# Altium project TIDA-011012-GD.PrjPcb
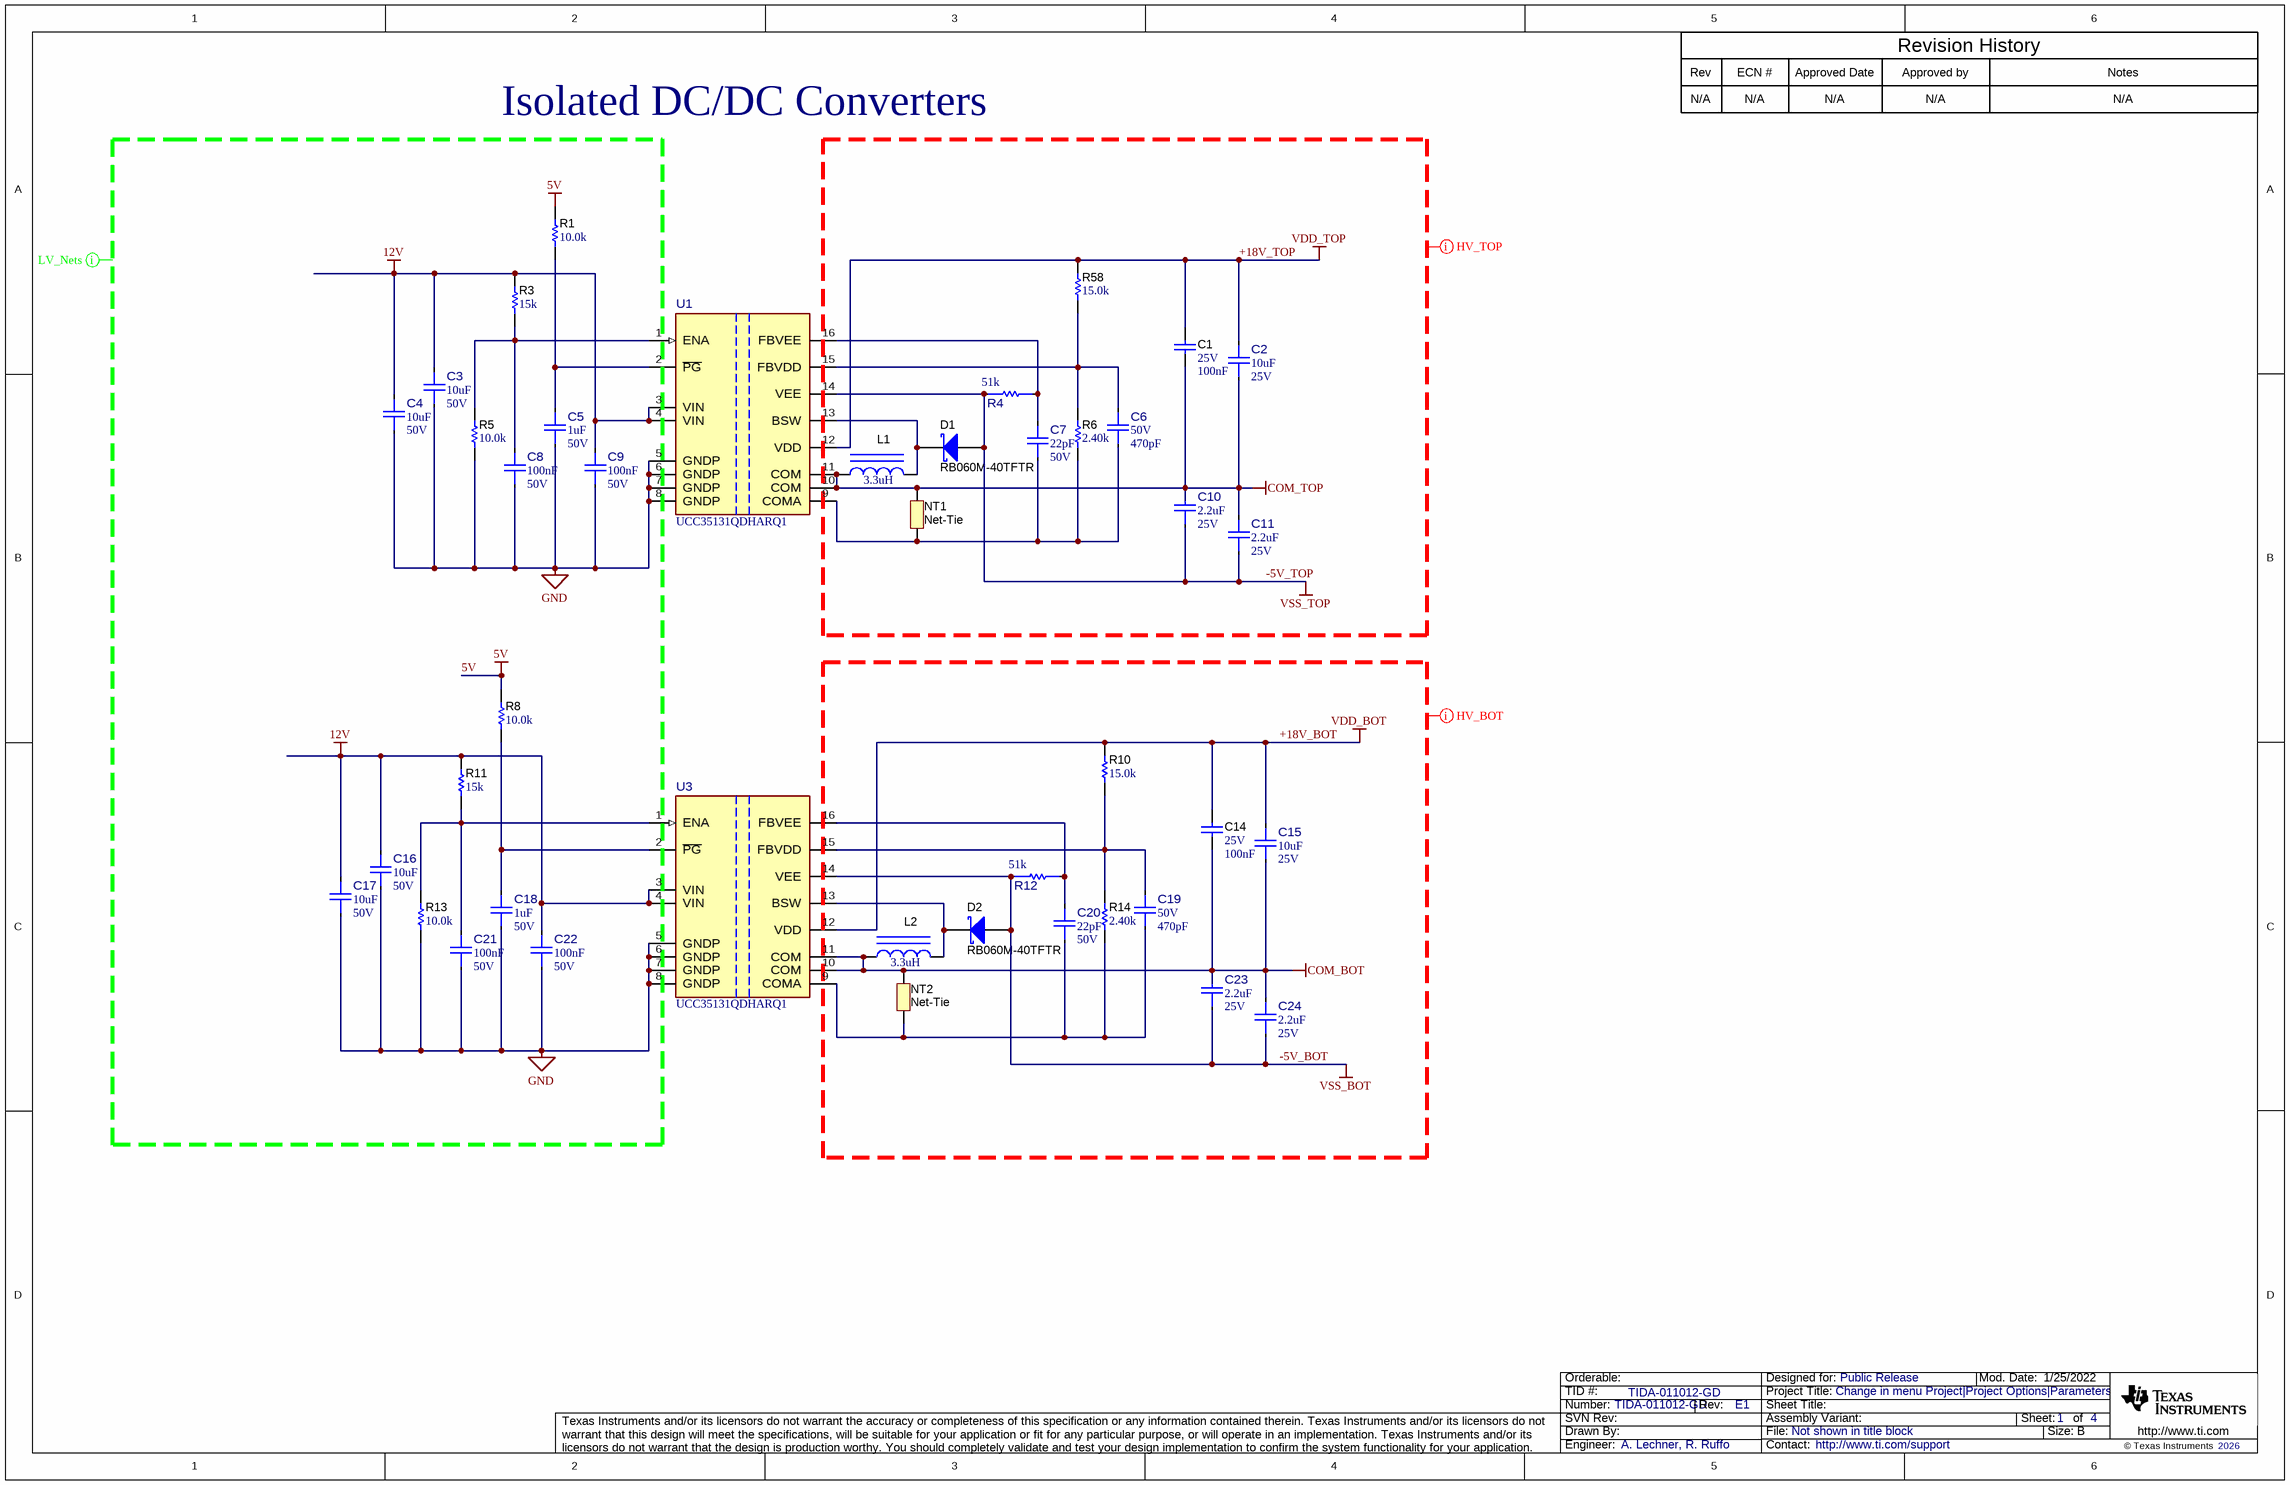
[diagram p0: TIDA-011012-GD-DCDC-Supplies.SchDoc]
TID: TIDA-011012-GD; TechSupport: http://www.ti.com/support; SCH_Rev: E1; PRJ_Title: Change in menu Project|Project Options|Parameters; PRJ_Number: TIDA-011012-GD; PRJ_Engineer: A. Lechner, R. Ruffo; PRJ_Customer: Public Release; PCB_Rev: E1; CopyrightYear: 2026
3 sheets, 153 parts. Net scope: global (net labels, ports and power ports of the same name join across sheets).
Board file: TIDA-011012-GD.PcbDoc
Sheets:
  TIDA-011012-GD-DCDC-Supplies.SchDoc
  TIDA-011012-GD-Gate-Drivers.SchDoc
  TIDA-011012-GD-Hardware.SchDoc

## Sheet TIDA-011012-GD-DCDC-Supplies.SchDoc
size 431 x 279 mm; Date: Not shown in title block; ApprovedBy: Not shown in title block; CheckedBy: Not shown in title block; Author: Not shown in title block; CompanyName: Not shown in title block; Engineer: Not shown in title block; Organization: Not shown in title block; Address1: Not shown in title block; Address2: Not shown in title block; Address3: Not shown in title block; Address4: Not shown in title block; DocumentNumber: 1; Revision: Use project parameter SCH_Rev; SheetNumber: 1; SheetTotal: 4; PageSetup: Record=PageOptions¦CenterHorizontal=True¦CenterVertical=True¦PrintScale=1.00¦XCorrection=1.00¦YCorrection=1.00¦PrintKind=0¦BorderSize=5000000¦LeftOffset=0¦BottomOffset=0¦Orientation=2¦PaperLength=1000¦PaperWidth=1000¦Scale=100¦PaperSource=15¦PrintQuality=600¦MediaType=1¦DitherType=10¦PaperKind=Letter¦PrintScaleMode=1

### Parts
C1  VDC_V: 25V  Cap_F: 100nF  [0603]  (hidden comment: GCM188R71E104KA57D)
C2  ValueDisplayed: 10uF  VDC_V: 25V  [FP-KGM31HR71E106KU_1206-MFG]  (hidden comment: KGM31HR71E106KU)
C3  ValueDisplayed: 10uF  VDC_V: 50V  [FP-GMC31X7R106K50NT_1206-MFG]  (hidden comment: GMC31X7R106K50NT)
C4  ValueDisplayed: 10uF  VDC_V: 50V  [FP-GMC31X7R106K50NT_1206-MFG]  (hidden comment: GMC31X7R106K50NT)
C5  ValueDisplayed: 1uF  VDC_V: 50V  [FP-C1206C105J5RECAUTO_1206-MFG]  (hidden comment: C1206C105J5RECAUTO)
C6  VDC_V: 50V  ValueDisplayed: 470pF  [FP-C0603X471F5GACTU_0603-MFG]  (hidden comment: C0603X471F5GACTU)
C7  ValueDisplayed: 22pF  VDC_V: 50V  [FP-VJ0603D220JLAAJ32_0603-IPC_C]  (hidden comment: VJ0603D220JLAAJ32)
C8  Cap_F: 100nF  VDC_V: 50V  [FP-KGM15BR71H104JT_0603-MFG]  (hidden comment: KGM15BR71H104JT)
C9  Cap_F: 100nF  VDC_V: 50V  [FP-KGM15BR71H104JT_0603-MFG]  (hidden comment: KGM15BR71H104JT)
C10  ValueDisplayed: 2.2uF  VDC_V: 25V  [FP-GRT188C71E225KE13D_0603-MFG]  (hidden comment: GRT188C71E225KE13D)
C11  ValueDisplayed: 2.2uF  VDC_V: 25V  [FP-CGA5L2X7R1E225K160AA_1206-MFG]  (hidden comment: CGA5L2X7R1E225K160AA)
C14  VDC_V: 25V  Cap_F: 100nF  [0603]  (hidden comment: GCM188R71E104KA57D)
C15  ValueDisplayed: 10uF  VDC_V: 25V  [FP-KGM31HR71E106KU_1206-MFG]  (hidden comment: KGM31HR71E106KU)
C16  ValueDisplayed: 10uF  VDC_V: 50V  [FP-GMC31X7R106K50NT_1206-MFG]  (hidden comment: GMC31X7R106K50NT)
C17  ValueDisplayed: 10uF  VDC_V: 50V  [FP-GMC31X7R106K50NT_1206-MFG]  (hidden comment: GMC31X7R106K50NT)
C18  ValueDisplayed: 1uF  VDC_V: 50V  [FP-C1206C105J5RECAUTO_1206-MFG]  (hidden comment: C1206C105J5RECAUTO)
C19  VDC_V: 50V  ValueDisplayed: 470pF  [FP-C0603X471F5GACTU_0603-MFG]  (hidden comment: C0603X471F5GACTU)
C20  ValueDisplayed: 22pF  VDC_V: 50V  [FP-VJ0603D220JLAAJ32_0603-IPC_C]  (hidden comment: VJ0603D220JLAAJ32)
C21  Cap_F: 100nF  VDC_V: 50V  [FP-KGM15BR71H104JT_0603-MFG]  (hidden comment: KGM15BR71H104JT)
C22  Cap_F: 100nF  VDC_V: 50V  [FP-KGM15BR71H104JT_0603-MFG]  (hidden comment: KGM15BR71H104JT)
C23  ValueDisplayed: 2.2uF  VDC_V: 25V  [FP-GRT188C71E225KE13D_0603-MFG]  (hidden comment: GRT188C71E225KE13D)
C24  ValueDisplayed: 2.2uF  VDC_V: 25V  [FP-CGA5L2X7R1E225K160AA_1206-MFG]  (hidden comment: CGA5L2X7R1E225K160AA)
D1  RB060M-40TFTR  [SOD-123]
D2  RB060M-40TFTR  [SOD-123]
L1  ValueDisplayed: 3.3uH  [0603]  (hidden comment: AIML-0603-3R3K-T)
L2  ValueDisplayed: 3.3uH  [0603]  (hidden comment: AIML-0603-3R3K-T)
NT1  Net-Tie  [Net-Tie_0805_HV_NoOverlay]  (net tie, no BOM)
NT2  Net-Tie  [Net-Tie_0805_HV_NoOverlay]  (net tie, no BOM)
R1  ValueDisplayed: 10.0k  [0603]  (hidden comment: ERJ-3EKF1002V)
R3  ValueDisplayed: 15k  [0603]  (hidden comment: RC0603JR-0715KL)
R4  value 51k  [FP-ERA-3AED513V_0603-MFG]  (hidden comment: ERA-3AED513V)
R5  ValueDisplayed: 10.0k  [0603]  (hidden comment: RT0603DRE0710KL)
R6  ValueDisplayed: 2.40k  [0603]  (hidden comment: RT0603DRE072K4L)
R8  ValueDisplayed: 10.0k  [0603]  (hidden comment: ERJ-3EKF1002V)
R10  ValueDisplayed: 15.0k  [0603]  (hidden comment: RT0603BRD0715KL)
R11  ValueDisplayed: 15k  [0603]  (hidden comment: RC0603JR-0715KL)
R12  value 51k  [FP-ERA-3AED513V_0603-MFG]  (hidden comment: ERA-3AED513V)
R13  ValueDisplayed: 10.0k  [0603]  (hidden comment: RT0603DRE0710KL)
R14  ValueDisplayed: 2.40k  [0603]  (hidden comment: RT0603DRE072K4L)
R58  ValueDisplayed: 15.0k  [0603]  (hidden comment: RT0603BRD0715KL)
U1  UCC35131QDHARQ1  [DHA0016A-MFG]
U3  UCC35131QDHARQ1  [DHA0016A-MFG]

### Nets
5V: R1.2 R8.2
12V: C3.2 C4.2 C9.2 C16.2 C17.2 C22.2 R3.2 R11.2 U1.3(VIN) U1.4(VIN) U3.3(VIN) U3.4(VIN)
+18V_BOT: C14.1 C15.2 R10.2 U3.12(VDD)  [also labelled VDD_BOT]
+18V_TOP: C1.1 C2.2 R58.2 U1.12(VDD)  [also labelled VDD_TOP]
-5V_BOT: C23.1 C24.1 D2.2(A) R12.1 U3.14(VEE)  [also labelled VSS_BOT]
-5V_TOP: C10.1 C11.1 D1.2(A) R4.1 U1.14(VEE)  [also labelled VSS_TOP]
COM_BOT: C14.2 C15.1 C23.2 C24.2 L2.1 NT2.2 U3.10(COM) U3.11(COM)  [project net KS2]
COM_TOP: C1.2 C2.1 C10.2 C11.2 L1.1 NT1.2 U1.10(COM) U1.11(COM)  [project net KS1]
GND: C3.1 C4.1 C5.1 C8.1 C9.1 C16.1 C17.1 C18.1 C21.1 C22.1 R5.1 R13.1 U1.5(GNDP) U1.6(GNDP) U1.7(GNDP) U1.8(GNDP) U3.5(GNDP) U3.6(GNDP) U3.7(GNDP) U3.8(GNDP)
NetC5_2: C5.2 R1.1 U1.2(~{PG})
NetC6_1: C6.1 C7.1 NT1.1 R6.1 U1.9(COMA)
NetC6_2: C6.2 R6.2 R58.1 U1.15(FBVDD)
NetC7_2: C7.2 R4.2 U1.16(FBVEE)
NetC8_2: C8.2 R3.1 R5.2 U1.1(ENA)
NetC18_2: C18.2 R8.1 U3.2(~{PG})
NetC19_1: C19.1 C20.1 NT2.1 R14.1 U3.9(COMA)
NetC19_2: C19.2 R10.1 R14.2 U3.15(FBVDD)
NetC20_2: C20.2 R12.2 U3.16(FBVEE)
NetC21_2: C21.2 R11.1 R13.2 U3.1(ENA)
NetD1_1: D1.1(K) L1.2 U1.13(BSW)
NetD2_1: D2.1(K) L2.2 U3.13(BSW)

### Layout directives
net class LV: 5V, 12V, GND
net class HV_TOP: +18V_TOP, -5V_TOP, COM_TOP, VDD_TOP, VSS_TOP
net class HV_BOT: +18V_BOT, -5V_BOT, COM_BOT, VDD_BOT, VSS_BOT

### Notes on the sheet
- Rev
- N/A
- ECN #
- Approved Date
- Approved by
- Revision History
- Notes
- Isolated DC/DC Converters

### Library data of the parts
C1 C14 = CMP-0084679-1: CAP, CERM, 0.1 µF, 25 V,+/- 10%, X7R, AEC-Q200 Grade 1, 0603; Manufacturer: MuRata; TaMin_C: -55°C; SizeY_mm: 0.8; Polarized: N; SizeArea_mm2: 1.28; SizeZ_mm: 1; SizeX_mm: 1.6; AEC Qualified: Y; AEC Category: Q200; Value: 0.1uF; ValueDisplayed: 0.1µF; TaMax_C: 125°C; U/M: EA; SizeAreaWB_mm2: 4.68
C2 C15 = CMP-0044202-1: 10 µF ±10% 25V Ceramic Capacitor X7R 1206 (3216 Metric); Manufacturer: KYOCERA AVX; AEC Qualified: No; Cap_F: 10µF; SizeZ_mm: 1.9mm; TempCo: 15%; Value: 10µF
C3 C4 C16 C17 = CMP-0093201-1: 10 µF ±10% 50V Ceramic Capacitor X7R 1206 (3216 Metric); Manufacturer: Cal-Chip Electronics; AEC Qualified: No; SizeZ_mm: 1.8mm; TempCo: 15%; Value: 10µF
C5 C18 = CMP-0094524-1: 1 µF ±5% 50V Ceramic Capacitor X7R 1206 (3216 Metric); Manufacturer: KEMET; TempCo: 15%; Cap_F: 1µF; AEC Grade: Grade 1; AEC Qualified: Yes; SizeZ_mm: 1.1mm; Value: 1µF
C6 C19 = CMP-0097612-1: Cap Ceramic 470pF 50V C0G 1% SMD 0603 125°C Paper T/R; Manufacturer: KEMET; SizeZ_mm: 0.95mm; TempCo: 30ppm/°C; AEC Qualified: No
C7 C20 = CMP-0039814-1: 22 pF ±5% 50V Ceramic Capacitor C0G, NP0 0603 (1608 Metric); Manufacturer: Vishay; AEC Grade: Grade 0; AEC Qualified: Yes; SizeZ_mm: 0.97mm; TempCo: 30ppm/°C; Value: 22pF
C8 C9 C21 C22 = CMP-0120061-1: 0.1 µF ±5% 50V Ceramic Capacitor X7R 0603 (1608 Metric); Manufacturer: KYOCERA AVX; AEC Qualified: No; SizeZ_mm: 0.94mm; TempCo: 15%; ValueDisplayed: 0.1uF; Value: 100nF
C10 C23 = CMP-0125378-1: Multi-Layer Ceramic Capacitor 2.2uF 25V X7S ±10% 0603 Paper T/R; Manufacturer: Murata; AEC Grade: Grade 1; AEC Qualified: Yes; Cap_F: 2.2µF; SizeZ_mm: 1mm; TempCo: 22%; Value: 2.2µF
C11 C24 = CMP-0090741-1: Cap Ceramic 2.2uF 25V X7R 10% Pad SMD 1206 +125°C Automotive T/R; Manufacturer: TDK; Cap_F: 2.2µF; Value: 2.2µF; Tolerance_%: 0.1%; TempCo: 15%; AEC Grade: Grade 1; AEC Qualified: Yes; SizeZ_mm: 1.9mm
D1 D2 = CMP-0028628-2: Diode, Schottky, 40 V, 2 A, SOD-123; Manufacturer: Rohm; Green_REACh: Incomplete; SizeX_mm: 3.85; SizeZ_mm: 1.35; TJmax_C: 150°C; Value1: 2A; SizeAreaWB_mm2: 13.095; SizeArea_mm2: 6.545; AEC Category: Q101; Value2: 0.56V; SizeY_mm: 1.7; Value: 40V; Vf_V: 560mV; Green_Lifecycle: Not Set
L1 L2 = CMP-0059575-1: Inductor, Multilayer, Ferrite, 3.3 uH, 0.015 A, 1.55 ohm, SMD; Manufacturer: Abracon Corporation; Green_Lifecycle: Active; SizeAreaWB_mm2: 4.68; DCR_ohm: 1.55; Green_REACh: Passed; Value: 3.3uH; Imax_A: 15mA; SizeZ_mm: 1; SizeX_mm: 1.6; SizeY_mm: 0.8; Value2: 0.015A; SizeArea_mm2: 1.28; Ind_H: 3.3µH; AEC Qualified: N; AEC Category: Q200
NT1 NT2 = CMP-0078142-6: Single point connection between nets.
R1 R8 = CMP-0022684-3: RES, 10.0 k, 1%, 0.1 W, 0603; Manufacturer: Panasonic; Power_W: 100mW; TempCo: 100 ppm/C; Value_Code: 10k0; U/M: EA; Value: 10.0k; EIA_Code: E96; Res_ohm: 10k; SizeX_mm: 1.6; SizeY_mm: 0.8; SizeZ_mm: 1; Value2: 0.1W; SizeArea_mm2: 1.28; VDC_V: 75V; AEC Category: Q200
R3 R11 = CMP-0025890-5: RES, 15 k, 5%, 0.1 W, 0603; Manufacturer: Yageo; Power_W: 100mW; TempCo: 100 ppm/C; Value_Code: 15k0; Value: 15k; EIA_Code: E24; SizeX_mm: 1.6; SizeY_mm: 0.8; SizeZ_mm: 1; Value2: 0.1W; SizeArea_mm2: 1.28; AEC Qualified: N; VDC_V: 75V; AEC Category: Q200; SizeAreaWB_mm2: 4.68
R4 R12 = CMP-0031881-1: 51 kOhms ±0.5% 0.1W, 1/10W Chip Resistor 0603 (1608 Metric) Automotive AEC-Q200 Thin Film; Manufacturer: Panasonic; AEC Grade: Grade 0; AEC Qualified: Yes; Power_W: 100mW; SizeZ_mm: 0.55mm; TempCo: 25ppm/°C; VDC_V: 75V
R5 R13 = CMP-0024586-3: RES, 10.0 k, 0.5%, 0.1 W, 0603; Manufacturer: Yageo America; Power_W: 100mW; TempCo: 50 ppm/C; Value_Code: 10k0; U/M: EA; Value: 10.0k; EIA_Code: E192; Res_ohm: 10k; SizeX_mm: 1.6; SizeY_mm: 0.8; SizeZ_mm: 1; Value2: 0.1W; SizeArea_mm2: 1.28; VDC_V: 75V; AEC Category: Q200
R6 R14 = CMP-0025064-3: RES, 2.40 k, 0.5%, 0.1 W, 0603; Manufacturer: Yageo America; Power_W: 100mW; TempCo: 50 ppm/C; Value_Code: 2k40; U/M: EA; Value: 2.40k; EIA_Code: E192; Res_ohm: 2.4k; SizeX_mm: 1.6; SizeY_mm: 0.8; SizeZ_mm: 1; Value2: 0.1W; SizeArea_mm2: 1.28; VDC_V: 75V; AEC Category: Q200
R10 R58 = CMP-0023780-3: RES, 15.0 k, 0.1%, 0.1 W, 0603; Manufacturer: Yageo America; Power_W: 100mW; TempCo: 25 ppm/C; Value_Code: 15k0; U/M: EA; Value: 15.0k; EIA_Code: E192; Res_ohm: 15k; SizeX_mm: 1.6; SizeY_mm: 0.8; SizeZ_mm: 1; Value2: 0.1W; SizeArea_mm2: 1.28; VDC_V: 75V; AEC Category: Q200
U1 U3 = CMP-0126653-2: Automotive 2.0W, 12V VIN, High-Density, > 5kVRMS, Isolated DC/DC Module; Manufacturer: Texas Instruments; SizeZ_mm: 2.6mm; AEC Qualified: Yes; AEC Grade: Grade 1; Max Supply Voltage: 20V; Min Supply Voltage: 5.5V; Number Of Outputs: 2; Output Type: AdjustableProgrammable; Output Voltage: -2-8/12-18V; Standoff Height: 0.1mm; TaMax_C: +125°C; TaMin_C: -40°C; TJmax_C: +150°C; AEC Category: Q200; CompType: IC

## Sheet TIDA-011012-GD-Gate-Drivers.SchDoc
size 558 x 431 mm; Date: Not shown in title block; ApprovedBy: Not shown in title block; CheckedBy: Not shown in title block; Author: Not shown in title block; CompanyName: Not shown in title block; Engineer: Not shown in title block; Organization: Not shown in title block; Address1: Not shown in title block; Address2: Not shown in title block; Address3: Not shown in title block; Address4: Not shown in title block; DocumentNumber: 2; Revision: Use project parameter SCH_Rev; SheetNumber: 2; SheetTotal: 3; PageSetup: Record=PageOptions¦CenterHorizontal=True¦CenterVertical=True¦PrintScale=1.00¦XCorrection=1.00¦YCorrection=1.00¦PrintKind=0¦BorderSize=5000000¦LeftOffset=0¦BottomOffset=0¦Orientation=2¦PaperLength=1000¦PaperWidth=1000¦Scale=100¦PaperSource=15¦PrintQuality=600¦MediaType=1¦DitherType=10¦PaperKind=Letter¦PrintScaleMode=1
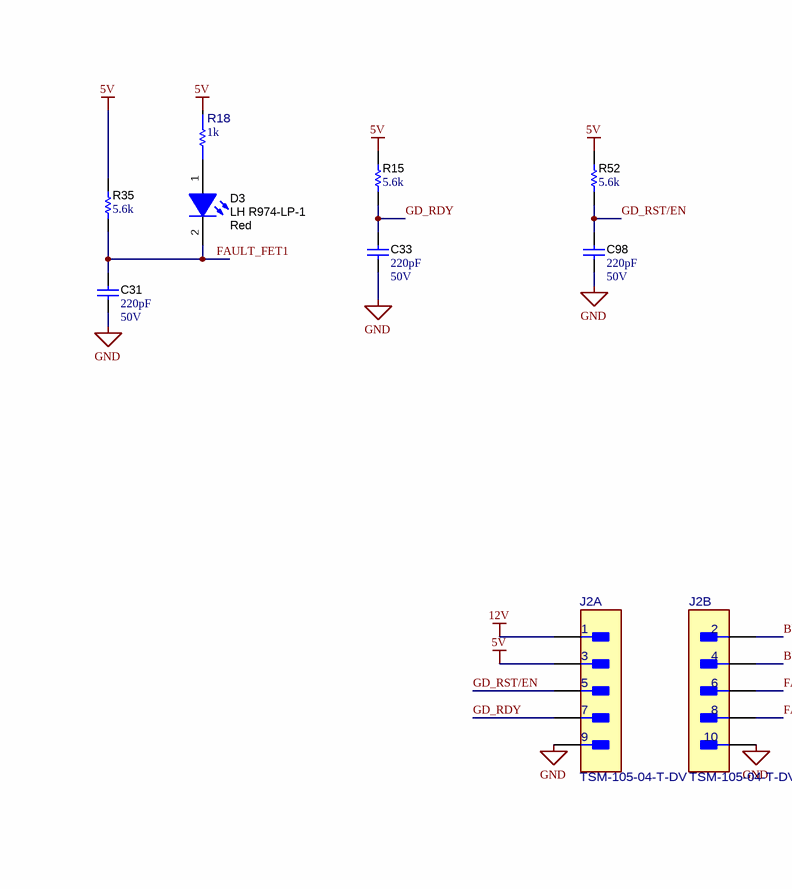
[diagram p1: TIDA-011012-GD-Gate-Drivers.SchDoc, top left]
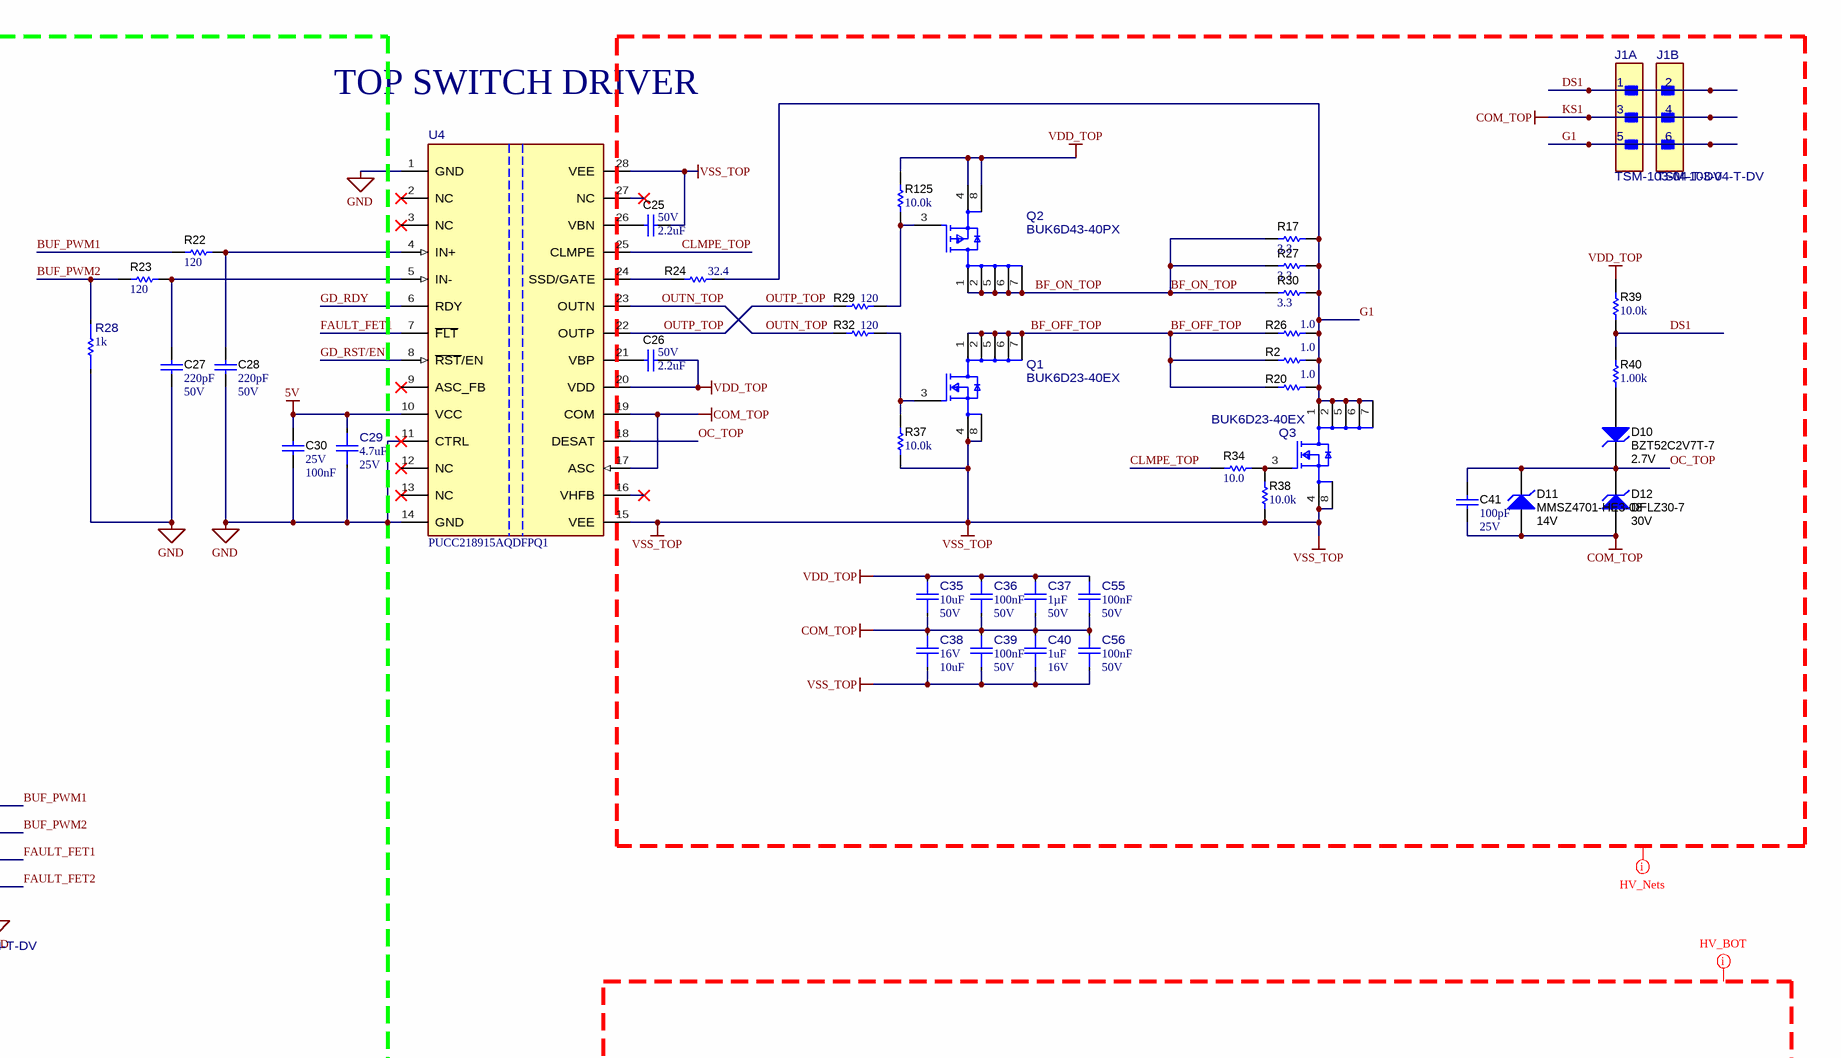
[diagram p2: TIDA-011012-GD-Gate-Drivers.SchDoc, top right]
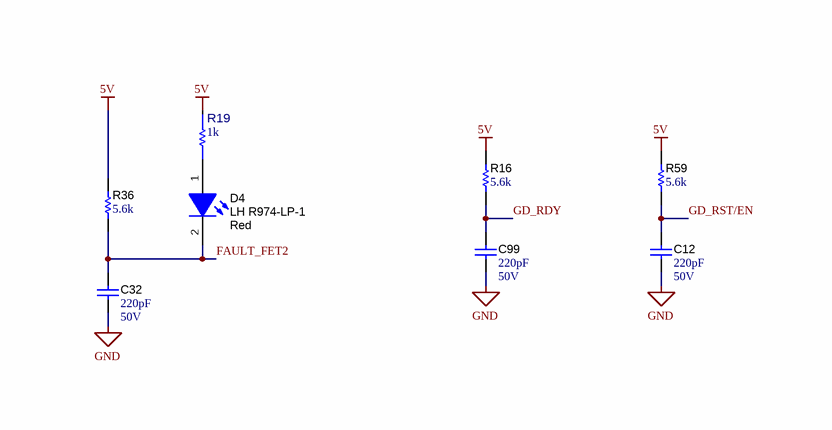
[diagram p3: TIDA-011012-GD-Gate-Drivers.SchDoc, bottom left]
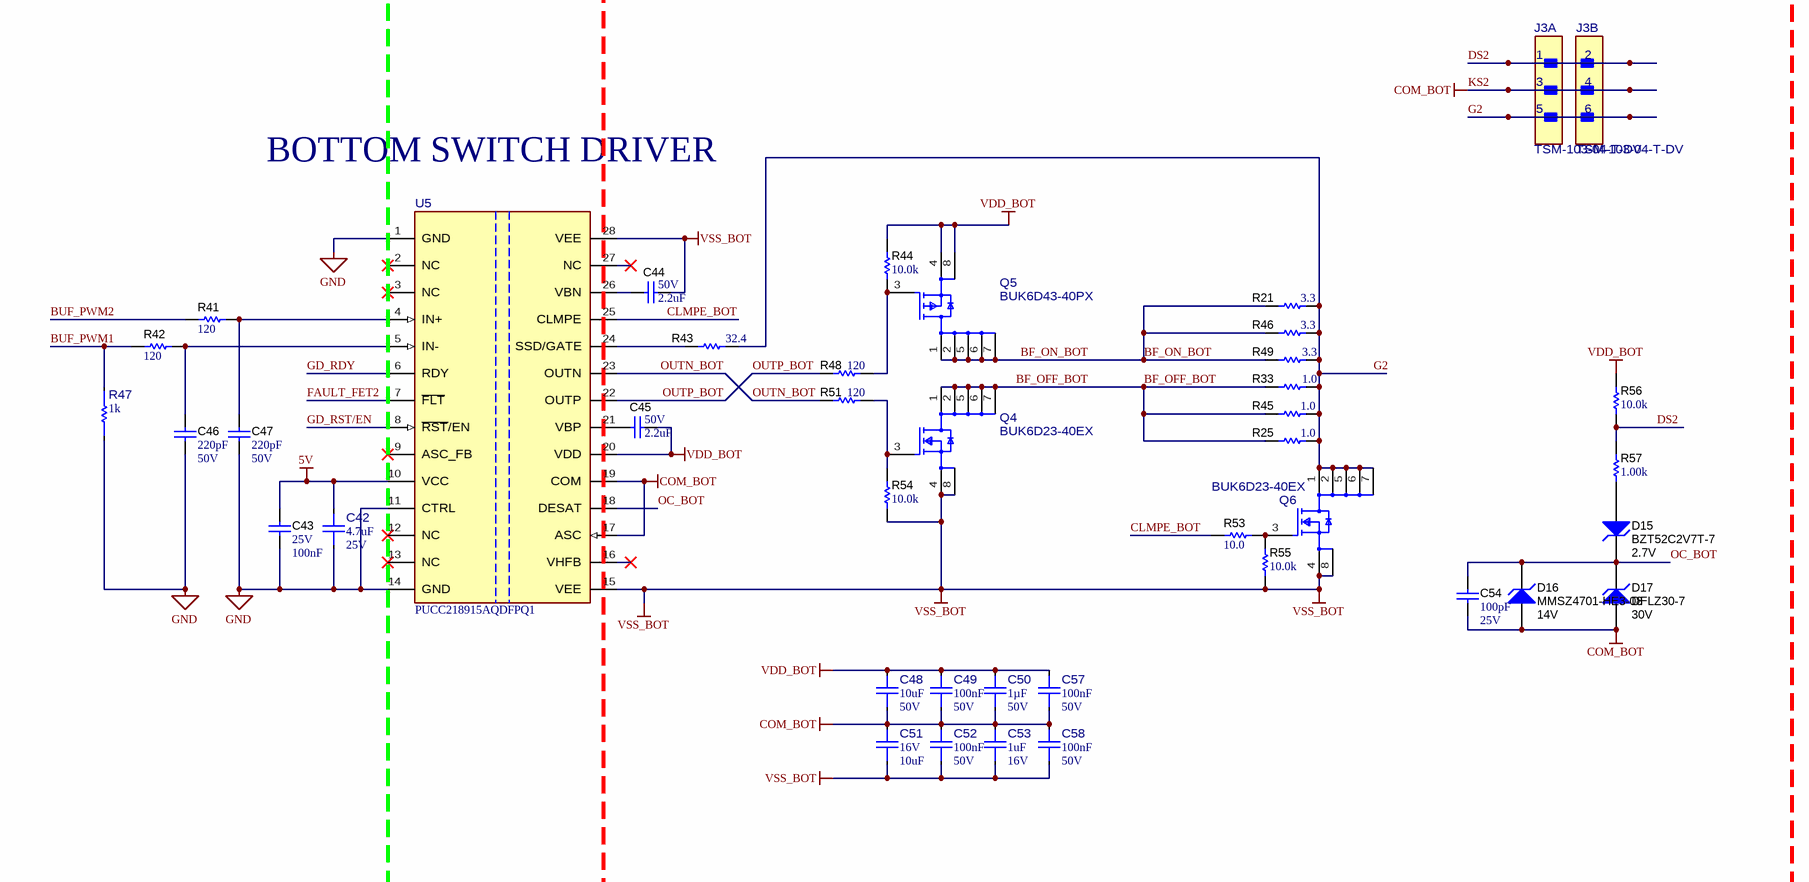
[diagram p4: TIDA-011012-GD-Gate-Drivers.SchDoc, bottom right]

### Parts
C12  Cap_F: 220pF  VDC_V: 50V  [0603]  (hidden comment: C0603C221K5RACTU)
C25  VDC_V: 50V  ValueDisplayed: 2.2uF  [0603]  (hidden comment: GRT188R61H225KE13D)
C26  VDC_V: 50V  ValueDisplayed: 2.2uF  [0603]  (hidden comment: GRT188R61H225KE13D)
C27  Cap_F: 220pF  VDC_V: 50V  [0603]  (hidden comment: C0603C221K5RACTU)
C28  Cap_F: 220pF  VDC_V: 50V  [0603]  (hidden comment: C0603C221K5RACTU)
C29  ValueDisplayed: 4.7uF  VDC_V: 25V  [FP-GRM188R61E475KE15D_0603-MFG]  (hidden comment: GRM188R61E475KE15D)
C30  VDC_V: 25V  Cap_F: 100nF  [0603]  (hidden comment: GCM188R71E104KA57D)
C31  Cap_F: 220pF  VDC_V: 50V  [0603]  (hidden comment: C0603C221K5RACTU)
C32  Cap_F: 220pF  VDC_V: 50V  [0603]  (hidden comment: C0603C221K5RACTU)
C33  Cap_F: 220pF  VDC_V: 50V  [0603]  (hidden comment: C0603C221K5RACTU)
C35  ValueDisplayed: 10uF  VDC_V: 50V  [FP-GMC31X7R106K50NT_1206-MFG]  (hidden comment: GMC31X7R106K50NT)
C36  Cap_F: 100nF  VDC_V: 50V  [FP-C0805C104K5RAC7800_0805-MFG]  (hidden comment: C0805C104K5RAC7800)
C37  Cap_F: 1µF  VDC_V: 50V  [FP-CL10B105KB9VPJC_0603-MFG]  (hidden comment: CL10B105KB9VPJC)
C38  VDC_V: 16V  ValueDisplayed: 10uF  [FP-C1206C106J4RACAUTO_1206-MFG]  (hidden comment: C1206C106J4RACAUTO)
C39  Cap_F: 100nF  VDC_V: 50V  [FP-C0805C104K5RAC7800_0805-MFG]  (hidden comment: C0805C104K5RAC7800)
C40  ValueDisplayed: 1uF  VDC_V: 16V  [FP-GRM188C71C105KA12D_0603-MFG]  (hidden comment: GRM188C71C105KA12D)
C41  Cap_F: 100pF  VDC_V: 25V  [0603]  (hidden comment: 06033C101KAT2A)
C42  ValueDisplayed: 4.7uF  VDC_V: 25V  [FP-GRM188R61E475KE15D_0603-MFG]  (hidden comment: GRM188R61E475KE15D)
C43  VDC_V: 25V  Cap_F: 100nF  [0603]  (hidden comment: GCM188R71E104KA57D)
C44  VDC_V: 50V  ValueDisplayed: 2.2uF  [0603]  (hidden comment: GRT188R61H225KE13D)
C45  VDC_V: 50V  ValueDisplayed: 2.2uF  [0603]  (hidden comment: GRT188R61H225KE13D)
C46  Cap_F: 220pF  VDC_V: 50V  [0603]  (hidden comment: C0603C221K5RACTU)
C47  Cap_F: 220pF  VDC_V: 50V  [0603]  (hidden comment: C0603C221K5RACTU)
C48  ValueDisplayed: 10uF  VDC_V: 50V  [FP-GMC31X7R106K50NT_1206-MFG]  (hidden comment: GMC31X7R106K50NT)
C49  Cap_F: 100nF  VDC_V: 50V  [FP-C0805C104K5RAC7800_0805-MFG]  (hidden comment: C0805C104K5RAC7800)
C50  Cap_F: 1µF  VDC_V: 50V  [FP-CL10B105KB9VPJC_0603-MFG]  (hidden comment: CL10B105KB9VPJC)
C51  VDC_V: 16V  ValueDisplayed: 10uF  [FP-C1206C106J4RACAUTO_1206-MFG]  (hidden comment: C1206C106J4RACAUTO)
C52  Cap_F: 100nF  VDC_V: 50V  [FP-C0805C104K5RAC7800_0805-MFG]  (hidden comment: C0805C104K5RAC7800)
C53  ValueDisplayed: 1uF  VDC_V: 16V  [FP-GRM188C71C105KA12D_0603-MFG]  (hidden comment: GRM188C71C105KA12D)
C54  Cap_F: 100pF  VDC_V: 25V  [0603]  (hidden comment: 06033C101KAT2A)
C55  Cap_F: 100nF  VDC_V: 50V  [FP-C0603C104K5RAC3121_0603-MFG]  (hidden comment: C0603C104K5RAC3121)
C56  Cap_F: 100nF  VDC_V: 50V  [FP-C0603C104K5RAC3121_0603-MFG]  (hidden comment: C0603C104K5RAC3121)
C57  Cap_F: 100nF  VDC_V: 50V  [FP-C0603C104K5RAC3121_0603-MFG]  (hidden comment: C0603C104K5RAC3121)
C58  Cap_F: 100nF  VDC_V: 50V  [FP-C0603C104K5RAC3121_0603-MFG]  (hidden comment: C0603C104K5RAC3121)
C98  Cap_F: 220pF  VDC_V: 50V  [0603]  (hidden comment: C0603C221K5RACTU)
C99  Cap_F: 220pF  VDC_V: 50V  [0603]  (hidden comment: C0603C221K5RACTU)
D3  LH R974-LP-1  value Red  [LH_R974_Red]
D4  LH R974-LP-1  value Red  [LH_R974_Red]
D10  BZT52C2V7T-7  value 2.7V  [SOD-523]
D11  MMSZ4701-HE3-08  value 14V  [SOD-123]
D12  DFLZ30-7  value 30V  [PowerDI123]
D15  BZT52C2V7T-7  value 2.7V  [SOD-523]
D16  MMSZ4701-HE3-08  value 14V  [SOD-123]
D17  DFLZ30-7  value 30V  [PowerDI123]
J1  TSM-103-04-T-DV  [FP-TSM-103-04-T-DV_HDR10-MFG]  (parts A,B of 2)
J2  TSM-105-04-T-DV  [FP-TSM-105-04-T-DV_HDR10-MFG]  (parts A,B of 2)
J3  TSM-103-04-T-DV  [FP-TSM-103-04-T-DV_HDR10-MFG]  (parts A,B of 2)
Q1  BUK6D23-40EX  [FP-BUK6D23-40EX_SOT1220-MFG]
Q2  BUK6D43-40PX  [FP-BUK6D43-40PX_SOT1220-MFG]
Q3  BUK6D23-40EX  [FP-BUK6D23-40EX_SOT1220-MFG]
Q4  BUK6D23-40EX  [FP-BUK6D23-40EX_SOT1220-MFG]
Q5  BUK6D43-40PX  [FP-BUK6D43-40PX_SOT1220-MFG]
Q6  BUK6D23-40EX  [FP-BUK6D23-40EX_SOT1220-MFG]
R2  ValueDisplayed: 1.0  [1206]  (hidden comment: CRM1206-JW-1R0ELF)
R15  ValueDisplayed: 5.6k  [0603]  (hidden comment: RC0603JR-075K6L)
R16  ValueDisplayed: 5.6k  [0603]  (hidden comment: RC0603JR-075K6L)
R17  ValueDisplayed: 3.3  [1206]  (hidden comment: CRCW12063R30JNEA)
R18  Res_ohm: 1k  [FP-ERJ-3GEYJ102V_0603-MFG]  (hidden comment: ERJ-3GEYJ102V)
R19  Res_ohm: 1k  [FP-ERJ-3GEYJ102V_0603-MFG]  (hidden comment: ERJ-3GEYJ102V)
R20  ValueDisplayed: 1.0  [1206]  (hidden comment: CRM1206-JW-1R0ELF)
R21  ValueDisplayed: 3.3  [1206]  (hidden comment: CRCW12063R30JNEA)
R22  ValueDisplayed: 120  [0603]  (hidden comment: RT0603BRD07120RL)
R23  ValueDisplayed: 120  [0603]  (hidden comment: RT0603BRD07120RL)
R24  ValueDisplayed: 32.4  [1206]  (hidden comment: CRCW120632R4FKEA)
R25  ValueDisplayed: 1.0  [1206]  (hidden comment: CRM1206-JW-1R0ELF)
R26  ValueDisplayed: 1.0  [1206]  (hidden comment: CRM1206-JW-1R0ELF)
R27  ValueDisplayed: 3.3  [1206]  (hidden comment: CRCW12063R30JNEA)
R28  Res_ohm: 1k  [FP-ERJ-3GEYJ102V_0603-MFG]  (hidden comment: ERJ-3GEYJ102V)
R29  ValueDisplayed: 120  [0603]  (hidden comment: RT0603BRD07120RL)
R30  ValueDisplayed: 3.3  [1206]  (hidden comment: CRCW12063R30JNEA)
R32  ValueDisplayed: 120  [0603]  (hidden comment: RT0603BRD07120RL)
R33  ValueDisplayed: 1.0  [1206]  (hidden comment: CRM1206-JW-1R0ELF)
R34  ValueDisplayed: 10.0  [0603]  (hidden comment: RC0603FR-0710RL)
R35  ValueDisplayed: 5.6k  [0603]  (hidden comment: RC0603JR-075K6L)
R36  ValueDisplayed: 5.6k  [0603]  (hidden comment: RC0603JR-075K6L)
R37  ValueDisplayed: 10.0k  [0603]  (hidden comment: ERJ-3EKF1002V)
R38  ValueDisplayed: 10.0k  [0603]  (hidden comment: ERJ-3EKF1002V)
R39  ValueDisplayed: 10.0k  [0603]  (hidden comment: ERJ-3EKF1002V)
R40  ValueDisplayed: 1.00k  [0603]  (hidden comment: ERJ-3EKF1001V)
R41  ValueDisplayed: 120  [0603]  (hidden comment: RT0603BRD07120RL)
R42  ValueDisplayed: 120  [0603]  (hidden comment: RT0603BRD07120RL)
R43  ValueDisplayed: 32.4  [1206]  (hidden comment: CRCW120632R4FKEA)
R44  ValueDisplayed: 10.0k  [0603]  (hidden comment: ERJ-3EKF1002V)
R45  ValueDisplayed: 1.0  [1206]  (hidden comment: CRM1206-JW-1R0ELF)
R46  ValueDisplayed: 3.3  [1206]  (hidden comment: CRCW12063R30JNEA)
R47  Res_ohm: 1k  [FP-ERJ-3GEYJ102V_0603-MFG]  (hidden comment: ERJ-3GEYJ102V)
R48  ValueDisplayed: 120  [0603]  (hidden comment: RT0603BRD07120RL)
R49  ValueDisplayed: 3.3  [1206]  (hidden comment: CRCW12063R30JNEA)
R51  ValueDisplayed: 120  [0603]  (hidden comment: RT0603BRD07120RL)
R52  ValueDisplayed: 5.6k  [0603]  (hidden comment: RC0603JR-075K6L)
R53  ValueDisplayed: 10.0  [0603]  (hidden comment: RC0603FR-0710RL)
R54  ValueDisplayed: 10.0k  [0603]  (hidden comment: ERJ-3EKF1002V)
R55  ValueDisplayed: 10.0k  [0603]  (hidden comment: ERJ-3EKF1002V)
R56  ValueDisplayed: 10.0k  [0603]  (hidden comment: ERJ-3EKF1002V)
R57  ValueDisplayed: 1.00k  [0603]  (hidden comment: ERJ-3EKF1001V)
R59  ValueDisplayed: 5.6k  [0603]  (hidden comment: RC0603JR-075K6L)
R125  ValueDisplayed: 10.0k  [0603]  (hidden comment: ERJ-3EKF1002V)
U4  PUCC218915AQDFPQ1  [DFP0028A-MFG]
U5  PUCC218915AQDFPQ1  [DFP0028A-MFG]

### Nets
5V: C29.2 C30.2 C42.2 C43.2 J2.3 R15.2 R16.2 R18.1 R19.1 R35.2 R36.2 R52.2 R59.2 U4.10(VCC) U5.10(VCC)
12V: J2.1
GND: C12.2 C27.2 C28.2 C29.1 C30.1 C31.2 C32.2 C33.2 C42.1 C43.1 C46.2 C47.2 C98.2 C99.2 J2.9 J2.10 R28.2 R47.2 U4.1(GND) U4.11(CTRL) U4.14(GND) U5.1(GND) U5.11(CTRL) U5.14(GND)
KS1: C35.1 C36.1 C37.1 C38.2 C39.2 C40.2 C41.2 C55.1 C56.2 D11.2(A) D12.2(A) J1.3 J1.4 U4.17(ASC) U4.19(COM)  [also labelled COM_TOP]
KS2: C48.1 C49.1 C50.1 C51.2 C52.2 C53.2 C54.2 C57.1 C58.2 D16.2(A) D17.2(A) J3.3 J3.4 U5.17(ASC) U5.19(COM)  [also labelled COM_BOT]
VDD_BOT: C45.1 C48.2 C49.2 C50.2 C57.2 Q5.4(S) Q5.8(S) R44.2 R56.2 U5.20(VDD)  [project net +18V_BOT]
VDD_TOP: C26.1 C35.2 C36.2 C37.2 C55.2 Q2.4(S) Q2.8(S) R39.2 R125.2 U4.20(VDD)  [project net +18V_TOP]
VSS_BOT: C44.1 C51.1 C52.1 C53.1 C58.1 Q4.4(S) Q4.8(S) Q6.4(S) Q6.8(S) R54.1 R55.2 U5.15(VEE) U5.28(VEE)  [project net -5V_BOT]
VSS_TOP: C25.1 C38.1 C39.1 C40.1 C56.1 Q1.4(S) Q1.8(S) Q3.4(S) Q3.8(S) R37.1 R38.1 U4.15(VEE) U4.28(VEE)  [project net -5V_TOP]
BF_OFF_BOT: Q4.1(D) Q4.2(D) Q4.5(D) Q4.6(D) Q4.7(D) R25.1 R33.1 R45.1
BF_OFF_TOP: Q1.1(D) Q1.2(D) Q1.5(D) Q1.6(D) Q1.7(D) R2.1 R20.1 R26.1
BF_ON_BOT: Q5.1(D) Q5.2(D) Q5.5(D) Q5.6(D) Q5.7(D) R21.1 R46.1 R49.1
BF_ON_TOP: Q2.1(D) Q2.2(D) Q2.5(D) Q2.6(D) Q2.7(D) R17.1 R27.1 R30.1
BUF_PWM1: J2.2 R22.1 R42.1 R47.1
BUF_PWM2: J2.4 R23.1 R28.1 R41.1
CLMPE_BOT: R53.1 U5.25(CLMPE)
CLMPE_TOP: R34.1 U4.25(CLMPE)
DS1: J1.1 J1.2 R39.1 R40.2
DS2: J3.1 J3.2 R56.1 R57.2
FAULT_FET1: C31.1 D3.2(K) J2.6 R35.1 U4.7(~{FLT})
FAULT_FET2: C32.1 D4.2(K) J2.8 R36.1 U5.7(~{FLT})
G1: J1.5 J1.6 Q3.1(D) Q3.2(D) Q3.5(D) Q3.6(D) Q3.7(D) R2.2 R17.2 R20.2 R24.2 R26.2 R27.2 R30.2
G2: J3.5 J3.6 Q6.1(D) Q6.2(D) Q6.5(D) Q6.6(D) Q6.7(D) R21.2 R25.2 R33.2 R43.2 R45.2 R46.2 R49.2
GD_RDY: C33.1 C99.1 J2.7 R15.1 R16.1 U4.6(RDY) U5.6(RDY)
GD_RST/EN: C12.1 C98.1 J2.5 R52.1 R59.1 U4.8(~{RST}/EN) U5.8(~{RST}/EN)
OC_BOT: C54.1 D15.1(K) D16.1(K) D17.1(K) U5.18(DESAT)
OC_TOP: C41.1 D10.1(K) D11.1(K) D12.1(K) U4.18(DESAT)
OUTN_BOT: R51.1 U5.23(OUTN)
OUTN_TOP: R32.1 U4.23(OUTN)
OUTP_BOT: R48.1 U5.22(OUTP)
OUTP_TOP: R29.1 U4.22(OUTP)
NetC25_2: C25.2 U4.26(VBN)
NetC26_2: C26.2 U4.21(VBP)
NetC27_1: C27.1 R23.2 U4.5(IN-)
NetC28_1: C28.1 R22.2 U4.4(IN+)
NetC44_2: C44.2 U5.26(VBN)
NetC45_2: C45.2 U5.21(VBP)
NetC46_1: C46.1 R42.2 U5.5(IN-)
NetC47_1: C47.1 R41.2 U5.4(IN+)
NetD3_1: D3.1(A) R18.2
NetD4_1: D4.1(A) R19.2
NetD10_2: D10.2(A) R40.1
NetD15_2: D15.2(A) R57.1
NetQ1_3: Q1.3(G) R32.2 R37.2
NetQ2_3: Q2.3(G) R29.2 R125.1
NetQ3_3: Q3.3(G) R34.2 R38.2
NetQ4_3: Q4.3(G) R51.2 R54.2
NetQ5_3: Q5.3(G) R44.1 R48.2
NetQ6_3: Q6.3(G) R53.2 R55.1
NetR24_1: R24.1 U4.24(SSD/GATE)
NetR43_1: R43.1 U5.24(SSD/GATE)

Not connected (* = marked no-connect by the designer): U4 2(NC)* 3(NC)* 9(ASC_FB)* 12(NC)* 13(NC)* 16(VHFB)* 27(NC)*; U5 2(NC)* 3(NC)* 9(ASC_FB)* 12(NC)* 13(NC)* 16(VHFB)* 27(NC)*

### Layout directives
net class LV: 5V, 12V, BUF_PWM1, BUF_PWM2, FAULT_FET1, FAULT_FET2, GD_RDY, GD_RST/EN, GND
net class HV_TOP: BF_OFF_TOP, BF_ON_TOP, CLMPE_TOP, COM_TOP, DS1, G1, KS1, OC_TOP, OUTN_TOP, OUTP_TOP, VDD_TOP, VSS_TOP
net class HV_BOT: BF_OFF_BOT, BF_ON_BOT, CLMPE_BOT, COM_BOT, DS2, G2, KS2, OC_BOT, OUTN_BOT, OUTP_BOT, VDD_BOT, VSS_BOT

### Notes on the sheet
- TOP SWITCH DRIVER
- BOTTOM SWITCH DRIVER

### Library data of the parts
C12 C27 C28 C31-C33 C46 C47 C98 C99 = CMP-0006895-4: CAP, CERM, 220 pF, 50 V, +/- 10%, X7R, 0603; Manufacturer: Kemet; TaMin_C: -55°C; Polarized: N; SizeAreaWB_mm2: 4.68; Value1: Unknown; U/M: EA; Value: 220pF; TaMax_C: 125°C; SizeZ_mm: 1; SizeX_mm: 1.6; SizeY_mm: 0.8; SizeArea_mm2: 1.28; AEC Category: Q200
C25 C26 C44 C45 = CMP-0007502-5: CAP, CERM, 2.2 uF, 50 V, +/- 10%, X5R, AEC-Q200 Grade 3, 0603; Manufacturer: MuRata; TaMin_C: -55°C; Polarized: N; SizeAreaWB_mm2: 4.68; Value1: Unknown; U/M: EA; Value: 2.2uF; TaMax_C: 85°C; SizeZ_mm: 1; SizeX_mm: 1.6; SizeY_mm: 0.8; SizeArea_mm2: 1.28; AEC Qualified: Y; Cap_F: 2.2µF; AEC Grade: 3; AEC Category: Q200
C29 C42 = CMP-0091702-1: 4.7µF ±10% 25V Ceramic Capacitor X5R 0603 (1608 Metric); Manufacturer: Murata; AEC Qualified: No; SizeZ_mm: 1mm; TempCo: 15%
C30 C43 = CMP-0084679-1: as C1 on sheet TIDA-011012-GD-DCDC-Supplies
C35 C48 = CMP-0093201-1: as C3 on sheet TIDA-011012-GD-DCDC-Supplies
C36 C39 C49 C52 = CMP-0120154-1: 0.1 µF ±10% 50V Ceramic Capacitor X7R 0805 (2012 Metric); Manufacturer: KEMET; AEC Qualified: No; SizeZ_mm: 0.88mm; TempCo: 15%; ValueDisplayed: 0.1uF; Value: 100nF
C37 C50 = CMP-0122257-1: 1 µF ±10% 50V Ceramic Capacitor X7R 0603 (1608 Metric); Manufacturer: Samsung; AEC Grade: Grade 1; AEC Qualified: Yes; SizeZ_mm: 1mm; TempCo: 15%; ValueDisplayed: 1uF; Value: 1µF
C38 C51 = CMP-0094514-1: 10 µF ±5% 16V Ceramic Capacitor X7R 1206 (3216 Metric); Manufacturer: KEMET; SizeZ_mm: 1.8mm; TempCo: 15%; Cap_F: 10µF; Value: 10µF; AEC Qualified: Yes; AEC Grade: Grade 1
C40 C53 = CMP-0122429-1: 1 µF ±10% 16V Ceramic Capacitor X7S 0603 (1608 Metric); Manufacturer: Murata; AEC Qualified: No; Cap_F: 1µF; SizeZ_mm: 0.9mm; TempCo: 22%; Value: 1µF
C41 C54 = CMP-0006751-4: CAP, CERM, 100 pF, 25 V, +/- 10%, X7R, 0603; Manufacturer: AVX; TaMin_C: -55°C; Polarized: N; SizeAreaWB_mm2: 4.68; Value1: Unknown; U/M: EA; Value: 100pF; TaMax_C: 125°C; SizeZ_mm: 1; SizeX_mm: 1.6; SizeY_mm: 0.8; SizeArea_mm2: 1.28; AEC Category: Q200
C55-C58 = CMP-0093594-1: 0.1 µF ±10% 50V Ceramic Capacitor X7R 0603 (1608 Metric); Manufacturer: KEMET; AEC Grade: Grade 1; AEC Qualified: Yes; ValueDisplayed: 0.1uF; SizeZ_mm: 0.87mm; TempCo: 15%; Value: 100nF
D3 D4 = CMP-0002983-3: LED, Red, SMD; Manufacturer: OSRAM; Ir_A: 100µA; Tjmax_C: 95°C; Vf_V: 1.8V; Value1: W; Vr_V: 5V; Io_A: 20mA; Angle: 160
D10 D15 = CMP-0005892-4: Diode, Zener, 2.7 V, 300 mW, SOD-523; Manufacturer: Diodes Inc.; SizeY_mm: 0.9; AEC Category: Q101; SizeX_mm: 1.7; Power_W: 300mW; Value1: 0.3W; SizeZ_mm: 0.65; SizeAreaWB_mm2: 5.13; RJA_CperW: 417; SizeArea_mm2: 1.53
D11 D16 = CMP-0077574-3: Diode, Zener, 14 V, 500 mW, AEC-Q101, SOD-123; Manufacturer: Vishay-Semiconductor; Power_W: 500mW; Value1: 0.5W; AEC Qualified: Y; SizeZ_mm: 1.35; SizeAreaWB_mm2: 13.095; SizeX_mm: 3.85; AEC Category: Q101; RJA_CperW: 340; SizeY_mm: 1.7; SizeArea_mm2: 6.545
D12 D17 = CMP-0005417-4: Diode, Zener, 30 V, 1 W, PowerDI123; Manufacturer: Diodes Inc.; SizeX_mm: 3.7; Power_W: 1W; SizeY_mm: 1.78; AEC Category: Q101; RJA_CperW: 110; SizeArea_mm2: 6.586; SizeZ_mm: 0.98; SizeAreaWB_mm2: 13.066
J1 J3 = CMP-0128886-1: Connector Header Surface Mount 6 position 0.100" (2.54mm); Manufacturer: Samtec; ContactFinish: Tin,Nickel; Row_Count: 2; AEC Grade: NA; AEC Qualified: No; Conn Gender: Male; Conn Orientation: Vertical; SizeZ_mm: 7.37mm
J2 = CMP-0128887-1: Connector Header Surface Mount 10 position 0.100" (2.54mm); Manufacturer: Samtec; ContactFinish: Tin,Nickel; Row_Count: 2; AEC Qualified: No; Conn Gender: Male; Conn Orientation: Vertical; SizeZ_mm: 7.37mm
Q1 Q3 Q4 Q6 = CMP-0120256-1: N-Channel 40 V 8A (Ta), 19A (Tc) 2.3W (Ta), 15W (Tc) Surface Mount DFN2020MD-6; Manufacturer: Nexperia; AEC Qualified: Yes; QgTyp_nC: 11nC @ 10V; Rdson45_ohm: 17m; SizeZ_mm: 0.65mm; VdsMax_V: 1.2V; Vgs_V: 20V; ChMode: False; AEC Grade: Grade 0; Drain To Source Breakdown Voltage: 40V; Input Capacitace At Vds: 582pF @ 20V; Number Of Channels: 1; Pulse Drain Current: 76A; Reverse Recovery Charge: 5.4nC; Reverse Recovery Time: 12.8ns; Rthja Max: 57K/W; TaMax_C: +175°C; TaMin_C: -55°C; Threshold Vgs Max: 2.7V; Threshold Vgs Min: 1.3V; Transconductance: 33S; Turn Off Delay Time: 12ns; Turn On Delay Time: 2ns; Typ Forward Diode Voltage: 0.8V
Q2 Q5 = CMP-0120257-1: P-Channel 40 V 6A (Ta) 15W (Tc) Surface Mount DFN2020MD-6; Manufacturer: Nexperia; AEC Qualified: Yes; IdsMax_A: -6A; QgTyp_nC: 24nC @ -10V; Rdson45_ohm: 30m; SizeZ_mm: 0.65mm; VdsMax_V: -1.2V; Vgs_V: 20V; ChMode: False; AEC Grade: Grade 0; Drain To Source Breakdown Voltage: -40V; Input Capacitace At Vds: 1260pF @ -20V; Number Of Channels: 1; Power_W: 2.3W; Pulse Drain Current: -56A; Reverse Recovery Charge: 8nC; Reverse Recovery Time: 15.6ns; Rthja Max: 57K/W; TaMax_C: +175°C; TaMin_C: -55°C; Threshold Vgs Max: -2.7V; Threshold Vgs Min: -1.4V; Transconductance: 33S; Turn Off Delay Time: 35ns; Turn On Delay Time: 9ns; Typ Forward Diode Voltage: -0.8V
R2 R20 R25 R26 R33 R45 = CMP-0018745-2: RES, 1.0, 5%, 0.5 W, 1206; Manufacturer: Bourns; Power_W: 500mW; TempCo: 150 ppm/C; Value_Code: 1R00; U/M: EA; Value: 1.0; EIA_Code: E24; Res_ohm: 1; SizeX_mm: 3.2; SizeY_mm: 1.6; SizeZ_mm: 1.35; Value2: 0.5W; SizeArea_mm2: 5.12; VDC_V: 1V; AEC Category: Q200
R15 R16 R35 R36 R52 R59 = CMP-0025933-5: RES, 5.6 k, 5%, 0.1 W, 0603; Manufacturer: Yageo; Power_W: 100mW; TempCo: 100 ppm/C; Value_Code: 5k60; Value: 5.6k; EIA_Code: E24; SizeX_mm: 1.6; SizeY_mm: 0.8; SizeZ_mm: 1; Value2: 0.1W; SizeArea_mm2: 1.28; AEC Qualified: N; VDC_V: 75V; AEC Category: Q200; SizeAreaWB_mm2: 4.68
R17 R21 R27 R30 R46 R49 = CMP-0018677-3: RES, 3.3, 5%, 0.25 W, AEC-Q200 Grade 0, 1206; Manufacturer: Vishay-Dale; Power_W: 250mW; TempCo: 200 ppm/C; Value_Code: 3R30; Value: 3.3; EIA_Code: E24; SizeX_mm: 3.2; SizeY_mm: 1.6; SizeZ_mm: 1.35; Value2: 0.25W; SizeArea_mm2: 5.12; AEC Qualified: Y; VDC_V: 200V; AEC Category: Q200; AEC Grade: 0
R18 R19 R28 R47 = CMP-0089144-1: 1 kOhms ±5% 0.1W, 1/10W Chip Resistor 0603 (1608 Metric) Automotive AEC-Q200 Thick Film; Manufacturer: Panasonic; Power_W: 100mW; AEC Qualified: Yes; Voltage: 75V; AEC Grade: Grade 0; SizeZ_mm: 0.55mm; TempCo: 200ppm/°C
R22 R23 R29 R32 R41 R42 R48 R51 = CMP-0023691-3: RES, 120, 0.1%, 0.1 W, 0603; Manufacturer: Yageo America; Power_W: 100mW; TempCo: 25 ppm/C; Value_Code: 120R; U/M: EA; Value: 120; EIA_Code: E192; SizeX_mm: 1.6; SizeY_mm: 0.8; SizeZ_mm: 1; Value2: 0.1W; SizeArea_mm2: 1.28; VDC_V: 75V; AEC Category: Q200
R24 R43 = CMP-0016910-3: RES, 32.4, 1%, 0.25 W, AEC-Q200 Grade 0, 1206; Manufacturer: Vishay-Dale; Power_W: 250mW; TempCo: 100 ppm/C; Value_Code: 32R4; Value: 32.4; EIA_Code: E96; SizeX_mm: 3.2; SizeY_mm: 1.6; SizeZ_mm: 1.35; Value2: 0.25W; SizeArea_mm2: 5.12; AEC Qualified: Y; VDC_V: 200V; AEC Category: Q200; AEC Grade: 0
R34 R53 = CMP-0022751-4: RES, 10.0, 1%, 0.1 W, 0603; Manufacturer: Yageo; Power_W: 100mW; TempCo: 100 ppm/C; Value_Code: 10R0; Value: 10.0; EIA_Code: E96; Res_ohm: 10; SizeX_mm: 1.6; SizeY_mm: 0.8; SizeZ_mm: 1; Value2: 0.1W; SizeArea_mm2: 1.28; AEC Qualified: N; VDC_V: 75V; AEC Category: Q200; SizeAreaWB_mm2: 4.68
R37-R39 R44 R54-R56 R125 = CMP-0022684-3: as R1 on sheet TIDA-011012-GD-DCDC-Supplies
R40 R57 = CMP-0022680-4: RES, 1.00 k, 1%, 0.1 W, 0603; Manufacturer: Panasonic; Power_W: 100mW; TempCo: 100 ppm/C; Value_Code: 1k00; U/M: EA; Value: 1.00k; EIA_Code: E96; Res_ohm: 1k; SizeX_mm: 1.6; SizeY_mm: 0.8; SizeZ_mm: 1; SizeArea_mm2: 1.28; VDC_V: 75V; AEC Category: Q200; Value2: 0.1W
U4 U5 = CMP-0128293-1: Single Channel Isolated Pre-Driver for SiC/IGBT with Active Protection; Manufacturer: Texas Instruments; SizeZ_mm: 2.6mm; AEC Qualified: Yes; AEC Grade: Grade 1; Max Supply Voltage: 28V; Min Supply Voltage: 3V; Number Of Drivers: 1; Standoff Height: 0.05mm; TaMax_C: +125°C; TaMin_C: -40°C; TJmax_C: +150°C; Turn Off Delay Time: 65ns

## Sheet TIDA-011012-GD-Hardware.SchDoc
size 431 x 279 mm; Date: Not shown in title block; ApprovedBy: Not shown in title block; CheckedBy: Not shown in title block; Author: Not shown in title block; CompanyName: Not shown in title block; Engineer: Not shown in title block; Organization: Not shown in title block; Address1: Not shown in title block; Address2: Not shown in title block; Address3: Not shown in title block; Address4: Not shown in title block; DocumentNumber: 3; Revision: Use project parameter SCH_Rev; SheetNumber: 3; SheetTotal: 3; PageSetup: Record=PageOptions¦CenterHorizontal=True¦CenterVertical=True¦PrintScale=1.00¦XCorrection=1.00¦YCorrection=1.00¦PrintKind=0¦BorderSize=5000000¦LeftOffset=0¦BottomOffset=0¦Orientation=2¦PaperLength=1000¦PaperWidth=1000¦Scale=100¦PaperSource=15¦PrintQuality=600¦MediaType=1¦DitherType=10¦PaperKind=Letter¦PrintScaleMode=1
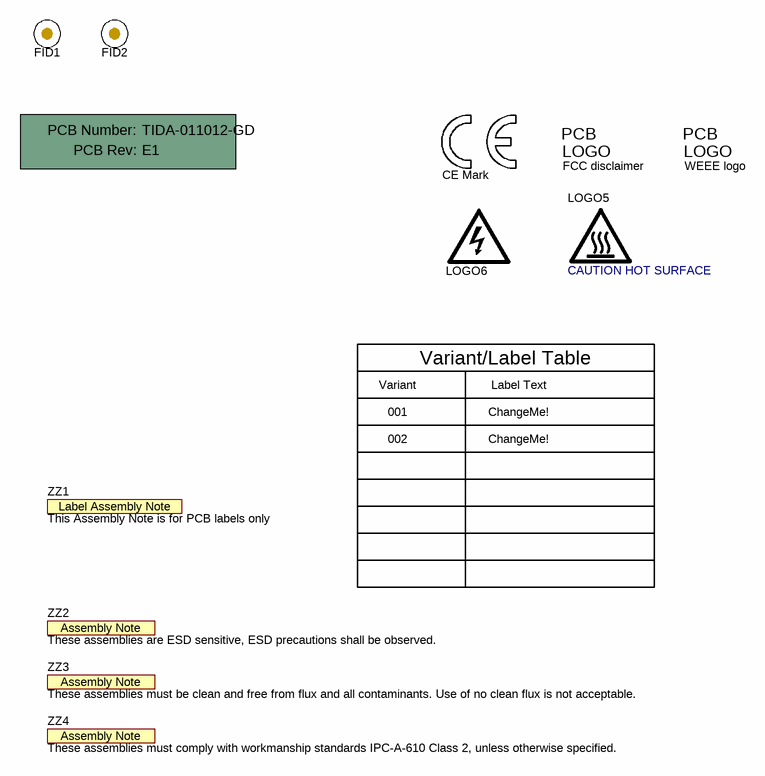
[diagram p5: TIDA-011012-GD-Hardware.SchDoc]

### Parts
!PCB  Printed Circuit Board  (value not drawn)  (mechanical)
FID1  Fiducial  [Fiducial10-20]  (value not drawn)
FID2  Fiducial  [Fiducial10-20]  (value not drawn)
Logo2  CE Mark  [CE_Mark_5mm]  (no BOM)
Logo3  FCC disclaimer  [FCC_disclaimer]  (no BOM)
Logo4  WEEE logo  [WEEE_Minimum]  (no BOM)
LOGO5  CAUTION HOT SURFACE  [IEC_HotSurface_Medium]  (no BOM)
LOGO6  DANGER HIGH VOLTAGE  [IEC_HighVoltage_Medium]  (value not drawn)  (no BOM)
ZZ1  This Assembly Note is for PCB labels only  [AssemblyNoteLabel]  (no BOM)
ZZ2  These assemblies are ESD sensitive, ESD precautions shall be observed.  [AssemblyNote]  (no BOM)
ZZ3  These assemblies must be clean and free from flux and all contaminants. Use of no clean flux is not acceptable.  [AssemblyNote]  (no BOM)
ZZ4  These assemblies must comply with workmanship standards IPC-A-610 Class 2, unless otherwise specified.  [AssemblyNote]  (no BOM)

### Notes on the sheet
- Variant
- Variant/Label Table
- Label Text
- 001
- 002
- ChangeMe!

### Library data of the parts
!PCB = CMP-0003618-2: Manufacturer: Any; PartNumber: TIDA-011012-GD
FID1 FID2 = CMP-0077181-1: Fiducial mark.  There is nothing to buy or mount.
Logo2 = CMP-0074844-1: SymbolCreator: a0412235
Logo3 = CMP-0074847-1: FCC_disclaimer; Library Reference: Logo
Logo4 = CMP-0074769-1
LOGO5 = CMP-0074837-2: IEC 61010-1 Hot Surface Warning; Manufacturer: Texas Instruments; SymbolCreator: a0412235; AEC Category: Q200; CompType: IC
LOGO6 = CMP-0074835-1: IEC 61010-1 High Voltage Warning; SymbolCreator: a0412235; Lib Reference: IEC_HighVoltage
ZZ1 = CMP-0003616-3
ZZ2 = CMP-0077236-1
ZZ3 = CMP-0077237-1
ZZ4 = CMP-0077238-1

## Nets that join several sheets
5V: TIDA-011012-GD-DCDC-Supplies (R1.2 R8.2), TIDA-011012-GD-Gate-Drivers (15 pins)
12V: TIDA-011012-GD-DCDC-Supplies (12 pins), TIDA-011012-GD-Gate-Drivers (J2.1)
+18V_BOT: TIDA-011012-GD-DCDC-Supplies (C14.1 C15.2 R10.2 U3.12), TIDA-011012-GD-Gate-Drivers (10 pins)
+18V_TOP: TIDA-011012-GD-DCDC-Supplies (C1.1 C2.2 R58.2 U1.12), TIDA-011012-GD-Gate-Drivers (10 pins)
-5V_BOT: TIDA-011012-GD-DCDC-Supplies (5 pins), TIDA-011012-GD-Gate-Drivers (13 pins)
-5V_TOP: TIDA-011012-GD-DCDC-Supplies (5 pins), TIDA-011012-GD-Gate-Drivers (13 pins)
GND: TIDA-011012-GD-DCDC-Supplies (20 pins), TIDA-011012-GD-Gate-Drivers (24 pins)
KS1: TIDA-011012-GD-DCDC-Supplies (8 pins), TIDA-011012-GD-Gate-Drivers (15 pins)
KS2: TIDA-011012-GD-DCDC-Supplies (8 pins), TIDA-011012-GD-Gate-Drivers (15 pins)

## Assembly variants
001: not fitted FID1 FID2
